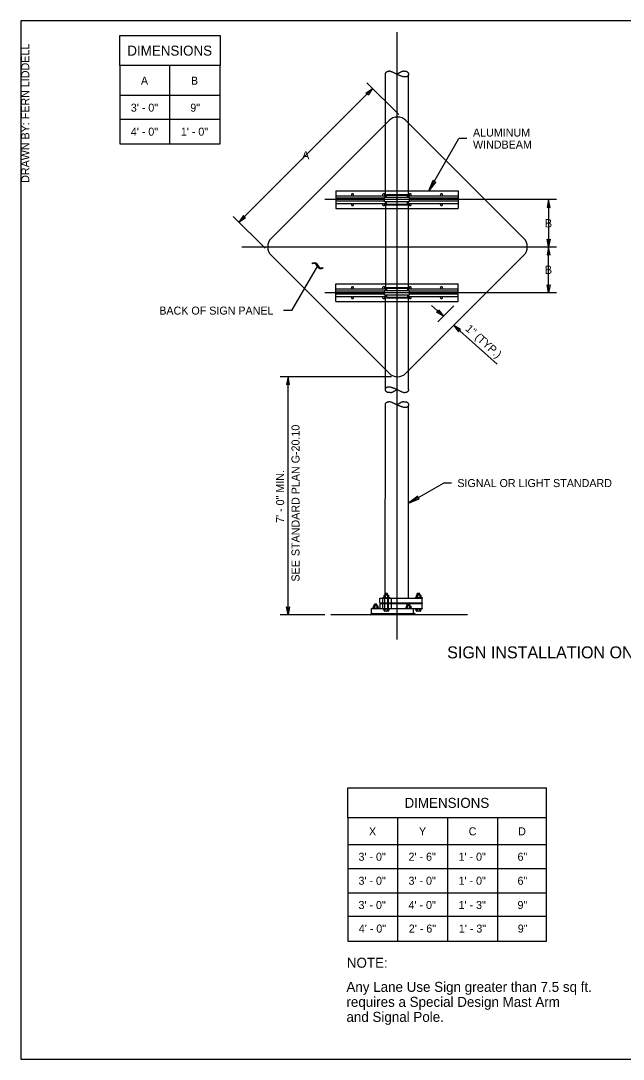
# Model space of a CAD drawing. Extents: x 99862 to 104211, y 98939 to 105076.
# Drawn here: x 99862 to 101066, y 103000 to 105076 of the extents above; entities that cross this region are included whole.
import ezdxf

# ---------------------------------------------------------------- set-up
doc = ezdxf.new("R2010")
doc.units = 0
for name, color, linetype in [('Level 1', 7, 'Continuous'), ('Level 15', 7, 'Continuous'), ('Level 18', 7, 'Continuous'), ('Level 19', 7, 'Continuous'), ('Level 2', 7, 'Continuous'), ('Level 20', 7, 'Continuous'), ('Level 3', 7, 'Continuous'), ('Level 40', 7, 'Continuous'), ('Level 6', 7, 'Continuous'), ('Level 60', 7, 'Continuous'), ('Level 62', 7, 'Continuous'), ('Level 7', 7, 'Continuous')]:
    doc.layers.add(name, color=color, linetype=linetype)

msp = doc.modelspace()

# ---------------------------------------------------------------- linework, layer by layer
at = {"layer": 'Level 1'}
for p, q in [((100590.9, 104868.6), (100362.5, 104640.3)), ((100590.9, 104868.6), (100598.3, 104876)), ((100598.3, 104876), (100598.3, 104876)), ((100632, 104876), (100631.9, 104876)), ((100631.9, 104876), (100637.1, 104870.9)), ((100867.7, 104640.3), (100637.1, 104870.9)), ((100362.5, 104606.6), (100590.9, 104378.3)), ((100637.1, 104376.1), (100867.7, 104606.6)), ((100598.3, 104370.9), (100590.9, 104378.3)), ((100598.3, 104370.9), (100598.3, 104370.9)), ((100637.1, 104376.1), (100631.9, 104370.9)), ((100631.9, 104370.9), (100631.9, 104370.9))]:
    msp.add_line(p, q, dxfattribs=at)
msp.add_lwpolyline([(99862, 102999.5), (103151, 102999.5), (103151, 105075.5), (99862, 105075.5)], close=True, dxfattribs=at)
for centre, start, end in [((100615.1, 104859.2), 44.9963, 134.9997), ((100379.4, 104623.5), 134.9966, 224.9936), ((100850.8, 104623.5), 314.9994, 44.9948), ((100615.1, 104387.7), 225, 314.9996)]:
    msp.add_arc(centre, 23.8, start, end, dxfattribs=at)
at = {"layer": 'Level 15'}
for p, q in [((100614.2, 103838.8), (100614.2, 105052.4)), ((100617.7, 104887.8), (100554.1, 104951.4)), ((100298.2, 104672.9), (100565.4, 104940.1)), ((100677.7, 104735.5), (100738, 104840)), ((100754, 104840), (100738, 104840)), ((100933.1, 104717.9), (100470, 104717.9)), ((100917.1, 104717.9), (100917.1, 104623.5)), ((100350.5, 104620.6), (100286.9, 104684.2)), ((100303.6, 104623.5), (100933.1, 104623.5)), ((100917.1, 104531.9), (100917.1, 104623.5)), ((100444.8, 104589.6), (100446, 104591.3)), ((100448.4, 104590.3), (100444.8, 104589.6)), ((100446, 104591.3), (100448.1, 104591.9)), ((100448.1, 104591.9), (100449.8, 104592.1)), ((100450.1, 104590.1), (100448.4, 104590.3)), ((100449.8, 104592.1), (100451.4, 104591.8)), ((100451.4, 104589.5), (100450.1, 104590.1)), ((100451.4, 104591.8), (100452.9, 104591)), ((100452.5, 104588.5), (100451.4, 104589.5)), ((100452.9, 104591), (100454.7, 104589.4)), ((100454.7, 104589.4), (100456.7, 104585.8)), ((100455.4, 104585.9), (100403.5, 104496.1)), ((100453.7, 104586.4), (100452.5, 104588.5)), ((100456, 104582.6), (100453.7, 104586.4)), ((100457.9, 104580.7), (100456, 104582.6)), ((100456.7, 104585.8), (100458.1, 104583.6)), ((100459.5, 104579.9), (100457.9, 104580.7)), ((100458.1, 104583.6), (100459.4, 104582.3)), ((100459.4, 104582.3), (100460.6, 104581.7)), ((100461.2, 104579.6), (100459.5, 104579.9)), ((100460.6, 104581.7), (100462, 104581.5)), ((100463, 104579.8), (100461.2, 104579.6)), ((100462, 104581.5), (100463.7, 104581.6)), ((100464.9, 104580.4), (100463, 104579.8)), ((100463.7, 104581.6), (100466, 104582.2)), ((100466, 104582.2), (100464.9, 104580.4)), ((100933.1, 104531.9), (100470, 104531.9)), ((100683, 104506), (100706.9, 104484.7)), ((100403.5, 104496.1), (100387.5, 104496.1)), ((100814.4, 104388.9), (100727.4, 104466.4)), ((100603.1, 104363.9), (100380.5, 104363.9)), ((100396.5, 103887.9), (100396.5, 104363.9)), ((100637.2, 104111.2), (100706.7, 104151.3)), ((100722.7, 104151.3), (100706.7, 104151.3)), ((100469.6, 103887.9), (100380.5, 103887.9))]:
    msp.add_line(p, q, dxfattribs=at)
for points in [[(100565.4, 104940.1), (100556.4, 104926.8), (100554.8, 104929.5), (100552.1, 104931.1)], [(100677.7, 104735.5), (100686.5, 104756.7), (100688.6, 104754.3), (100691.7, 104753.7)], [(100917.1, 104717.9), (100914, 104702.2), (100917.1, 104702.9), (100920.2, 104702.2)], [(100298.2, 104672.9), (100311.5, 104681.9), (100308.8, 104683.5), (100307.2, 104686.2)], [(100917.1, 104623.5), (100914, 104639.2), (100917.1, 104638.5), (100920.2, 104639.2)], [(100917.1, 104623.5), (100914, 104607.8), (100917.1, 104608.5), (100920.2, 104607.8)], [(100917.1, 104531.9), (100914, 104547.6), (100917.1, 104546.9), (100920.2, 104547.6)], [(100706.9, 104484.7), (100693.1, 104492.9), (100695.7, 104494.7), (100697.2, 104497.5)], [(100727.4, 104466.4), (100737.1, 104453.6), (100738.6, 104456.4), (100741.2, 104458.2)], [(100396.5, 104363.9), (100393.4, 104348.2), (100396.5, 104348.9), (100399.5, 104348.2)], [(100637.2, 104111.2), (100658.4, 104120), (100656, 104122.1), (100655.4, 104125.2)], [(100396.5, 103887.9), (100393.4, 103903.6), (100396.5, 103902.9), (100399.5, 103903.6)]]:
    msp.add_lwpolyline(points, close=True, dxfattribs=at)
msp.add_lwpolyline([(100727.9, 104505.8), (100695.6, 104473.4)], dxfattribs=at)
at = {"layer": 'Level 18'}
for p, q in [((100588, 103926.8), (100588, 103922.7)), ((100596.1, 103927.2), (100589.1, 103927.2)), ((100590.1, 103927.2), (100590.1, 103930.5)), ((100595.1, 103930.5), (100590.1, 103930.5)), ((100590.3, 103926.9), (100590.3, 103922.7)), ((100591.4, 103928.9), (100593.9, 103928.9)), ((100595, 103926.9), (100595, 103922.7)), ((100595.1, 103927.2), (100595.1, 103930.5)), ((100597.3, 103926.8), (100597.3, 103922.7)), ((100652.6, 103926.8), (100652.6, 103922.7)), ((100660.7, 103927.2), (100653.7, 103927.2)), ((100654.7, 103927.2), (100654.7, 103930.5)), ((100659.7, 103930.5), (100654.7, 103930.5)), ((100654.9, 103926.9), (100654.9, 103922.7)), ((100656, 103928.9), (100658.5, 103928.9)), ((100659.6, 103926.9), (100659.6, 103922.7)), ((100659.7, 103927.2), (100659.7, 103930.5)), ((100661.9, 103926.8), (100661.9, 103922.7)), ((100566.7, 103905.5), (100566.7, 103901.4)), ((100574.8, 103905.9), (100567.8, 103905.9)), ((100568.8, 103905.9), (100568.8, 103909.2)), ((100573.8, 103909.2), (100568.8, 103909.2)), ((100569, 103905.5), (100569, 103901.4)), ((100570.1, 103907.6), (100572.6, 103907.6)), ((100573.6, 103905.6), (100573.6, 103901.4)), ((100573.8, 103905.9), (100573.8, 103909.2)), ((100575.9, 103905.5), (100575.9, 103901.4)), ((100579.6, 103911.7), (100579.6, 103921.5)), ((100579.6, 103921.5), (100664.1, 103921.5)), ((100579.6, 103911.7), (100664.1, 103911.7)), ((100579.6, 103910.4), (100664.1, 103910.4)), ((100579.6, 103910.4), (100579.6, 103900.6)), ((100585.8, 103922.7), (100599.7, 103922.7)), ((100585.8, 103922.7), (100585.8, 103921.5)), ((100585.8, 103911.7), (100585.8, 103921.5)), ((100585.8, 103911.7), (100585.8, 103910.4)), ((100585.8, 103900.6), (100585.8, 103910.4)), ((100589.5, 103911.7), (100589.5, 103921.5)), ((100589.5, 103900.6), (100589.5, 103910.4)), ((100595.6, 103911.7), (100595.6, 103921.5)), ((100595.6, 103900.6), (100595.6, 103910.4)), ((100596.9, 103911.7), (100596.9, 103921.5)), ((100596.9, 103900.6), (100596.9, 103910.4)), ((100599.7, 103922.7), (100599.7, 103921.5)), ((100599.7, 103911.7), (100599.7, 103910.4)), ((100603, 103911.7), (100603, 103921.5)), ((100603, 103900.6), (100603, 103910.4)), ((100632.3, 103905.5), (100632.3, 103901.4)), ((100640.4, 103905.9), (100633.4, 103905.9)), ((100634.4, 103905.9), (100634.4, 103909.2)), ((100639.4, 103909.2), (100634.4, 103909.2)), ((100634.6, 103905.5), (100634.6, 103901.4)), ((100635.7, 103907.6), (100638.2, 103907.6)), ((100639.3, 103905.6), (100639.3, 103901.4)), ((100639.4, 103905.9), (100639.4, 103909.2)), ((100641.6, 103905.5), (100641.6, 103901.4)), ((100650.2, 103922.7), (100664.1, 103922.7)), ((100650.2, 103922.7), (100650.2, 103921.5)), ((100650.2, 103911.7), (100650.2, 103910.4)), ((100664.1, 103922.7), (100664.1, 103921.5)), ((100664.1, 103911.7), (100664.1, 103921.5)), ((100664.1, 103911.7), (100664.1, 103910.4)), ((100664.1, 103900.6), (100664.1, 103910.4)), ((100755.3, 103887.9), (100481.6, 103887.9)), ((100559.9, 103887.9), (100562.8, 103890.7)), ((100562.8, 103890.7), (100562.8, 103900.6)), ((100562.8, 103900.6), (100579.6, 103900.6)), ((100562.8, 103890.7), (100648.5, 103890.7)), ((100564, 103901.4), (100578.4, 103901.4)), ((100564, 103901.4), (100564, 103900.6)), ((100578.4, 103901.4), (100578.4, 103900.6)), ((100579.6, 103900.6), (100664.1, 103900.6)), ((100585.8, 103900.6), (100585.8, 103899.8)), ((100585.8, 103899.8), (100599.7, 103899.8)), ((100588.2, 103895.7), (100588.2, 103899.8)), ((100596.3, 103895.3), (100589.4, 103895.3)), ((100590.5, 103895.6), (100590.5, 103899.8)), ((100595.2, 103895.6), (100595.2, 103899.8)), ((100597.5, 103895.7), (100597.5, 103899.8)), ((100599.7, 103900.6), (100599.7, 103899.8)), ((100629.7, 103901.4), (100644, 103901.4)), ((100629.7, 103901.4), (100629.7, 103900.6)), ((100644, 103901.4), (100644, 103900.6)), ((100646.9, 103890.7), (100646.9, 103900.6)), ((100651.4, 103887.9), (100648.5, 103890.7)), ((100650.2, 103900.6), (100650.2, 103899.8)), ((100650.2, 103899.8), (100664.1, 103899.8)), ((100652.6, 103895.7), (100652.6, 103899.8)), ((100660.7, 103895.3), (100653.7, 103895.3)), ((100654.9, 103895.6), (100654.9, 103899.8)), ((100659.6, 103895.6), (100659.6, 103899.8)), ((100661.9, 103895.7), (100661.9, 103899.8)), ((100664.1, 103900.6), (100664.1, 103899.8))]:
    msp.add_line(p, q, dxfattribs=at)
for centre, radius, start, end in [((100589.2, 103925.4), 1.81, 52.3034, 130.9523), ((100592.7, 103919.5), 7.78, 72.912, 107.9146), ((100596.1, 103925.3), 1.95, 52.6587, 124.5047), ((100653.8, 103925.4), 1.81, 52.3034, 130.9523), ((100657.3, 103919.5), 7.78, 72.912, 107.9146), ((100660.7, 103925.3), 1.95, 52.6587, 124.5047), ((100567.9, 103904.1), 1.81, 52.3034, 130.9523), ((100571.4, 103898.1), 7.78, 72.912, 107.9146), ((100574.8, 103904), 1.95, 52.6587, 124.5047), ((100633.5, 103904.1), 1.81, 52.3034, 130.9523), ((100637, 103898.1), 7.78, 72.912, 107.9146), ((100640.4, 103904), 1.95, 52.6587, 124.5047), ((100589.4, 103897.1), 1.81, 229.0477, 307.6966), ((100592.9, 103903), 7.78, 252.0854, 287.088), ((100596.3, 103897.2), 1.95, 235.4953, 307.3413), ((100653.8, 103897.1), 1.81, 229.0477, 307.6966), ((100657.3, 103903), 7.78, 252.0854, 287.088), ((100660.7, 103897.2), 1.95, 235.4953, 307.3413)]:
    msp.add_arc(centre, radius, start, end, dxfattribs=at)
at = {"layer": 'Level 19'}
for p, q in [((100590.9, 104722.6), (100590.9, 104968.9)), ((100637.1, 104722.6), (100637.1, 104967.4)), ((100590.9, 104713.2), (100590.9, 104536.6)), ((100637.1, 104536.6), (100637.1, 104713.2)), ((100590.9, 104338.7), (100590.9, 104527.2)), ((100637.1, 104338.4), (100637.1, 104527.2)), ((100590.7, 103930.5), (100591, 104309.7)), ((100637.2, 103921.5), (100637.2, 104306.4))]:
    msp.add_line(p, q, dxfattribs=at)
for points in [[(100627.4, 104974.7), (100630.4, 104974.7)], [(100600.7, 104332.2), (100597.7, 104332.2)], [(100627.5, 104314), (100630.5, 104314)]]:
    msp.add_lwpolyline(points, dxfattribs=at)
for points in [[(100590.9, 104968.5), (100590.9, 104968.6), (100590.9, 104969), (100591, 104969.8), (100591.3, 104970.7), (100591.8, 104971.6), (100592.4, 104972.5), (100593.3, 104973.3), (100594.4, 104974), (100595.8, 104974.6), (100597, 104974.7), (100597.6, 104974.7)], [(100630.4, 104974.7), (100631, 104974.7), (100632.2, 104974.6), (100633.6, 104974), (100634.7, 104973.3), (100635.6, 104972.5), (100636.2, 104971.6), (100636.7, 104970.7), (100637, 104969.8), (100637.2, 104968.8), (100637.2, 104967.7), (100637, 104967), (100636.7, 104966.1), (100636.1, 104965.3), (100635.4, 104964.6), (100634.3, 104963.9), (100633, 104963.4), (100631.4, 104963.2), (100629.5, 104963.2), (100627.4, 104963.4), (100625.3, 104963.9), (100623.2, 104964.5), (100621.1, 104965.3), (100619.1, 104966.1), (100617.1, 104967), (100615.1, 104967.9), (100613.2, 104968.8), (100611.3, 104969.8), (100609.4, 104970.7), (100607.5, 104971.6), (100605.6, 104972.5), (100603.7, 104973.3), (100601.7, 104974), (100599.7, 104974.6), (100598.3, 104974.7), (100597.7, 104974.7)], [(100627.4, 104974.7), (100626.9, 104974.7), (100625.8, 104974.6), (100624.1, 104974), (100622.5, 104973.3), (100620.9, 104972.5), (100619.4, 104971.6), (100617.8, 104970.7), (100616.3, 104969.8), (100615, 104969), (100614.3, 104968.6), (100614.1, 104968.4)], [(100597.7, 104332.2), (100597.1, 104332.2), (100595.9, 104332.3), (100594.5, 104332.9), (100593.4, 104333.6), (100592.5, 104334.4), (100591.9, 104335.3), (100591.4, 104336.2), (100591.1, 104337.1), (100590.9, 104338.1), (100590.9, 104338.7), (100591.1, 104339.9), (100591.4, 104340.7), (100592, 104341.6), (100592.7, 104342.3), (100593.8, 104343), (100595.1, 104343.5), (100596.7, 104343.7), (100598.6, 104343.7), (100600.7, 104343.5), (100602.8, 104343), (100604.9, 104342.3), (100607, 104341.6), (100609, 104340.8), (100611, 104339.9), (100612.9, 104339), (100614.9, 104338.1), (100616.8, 104337.1), (100618.7, 104336.2), (100620.6, 104335.3), (100622.5, 104334.4), (100624.4, 104333.6), (100626.4, 104332.9), (100628.4, 104332.3), (100629.7, 104332.2), (100630.4, 104332.2)], [(100600.7, 104332.2), (100601.2, 104332.2), (100602.3, 104332.3), (100604, 104332.9), (100605.6, 104333.6), (100607.1, 104334.4), (100608.7, 104335.3), (100610.3, 104336.2), (100611.8, 104337.1), (100613.1, 104337.9), (100613.8, 104338.3), (100614, 104338.4)], [(100637.1, 104338.4), (100637.1, 104338.3), (100637.1, 104337.9), (100637, 104337.1), (100636.7, 104336.2), (100636.2, 104335.3), (100635.6, 104334.4), (100634.7, 104333.6), (100633.6, 104332.9), (100632.2, 104332.3), (100631, 104332.2), (100630.4, 104332.2)], [(100591, 104309.7), (100591, 104309.8), (100591.2, 104310.2), (100591.5, 104310.9), (100592.2, 104311.8), (100593.1, 104312.6), (100594.2, 104313.3), (100595.6, 104313.9), (100596.8, 104314), (100597.5, 104314)], [(100630.5, 104314), (100631.1, 104314), (100632.3, 104313.9), (100633.7, 104313.3), (100634.8, 104312.6), (100635.7, 104311.8), (100636.4, 104310.9), (100636.9, 104310), (100637.2, 104309), (100637.3, 104308.1), (100637.3, 104307.2), (100637.1, 104306.3), (100636.8, 104305.4), (100636.3, 104304.6), (100635.5, 104303.8), (100634.5, 104303.1), (100633.1, 104302.6), (100631.5, 104302.4), (100629.6, 104302.4), (100627.5, 104302.6), (100625.3, 104303.1), (100623.2, 104303.8), (100621.1, 104304.5), (100619, 104305.4), (100617, 104306.2), (100615.1, 104307.2), (100613.1, 104308.1), (100611.2, 104309), (100609.3, 104310), (100607.4, 104310.9), (100605.4, 104311.8), (100603.5, 104312.6), (100601.5, 104313.3), (100599.4, 104313.9), (100598.1, 104314), (100597.5, 104314)], [(100627.5, 104314), (100626.9, 104314), (100625.8, 104313.9), (100624.1, 104313.3), (100622.5, 104312.6), (100620.9, 104311.8), (100619.3, 104310.9), (100617.8, 104310), (100616.2, 104309), (100615, 104308.3), (100614.2, 104307.8), (100614, 104307.7)]]:
    msp.add_open_spline(points, degree=3, dxfattribs=at)
at = {"layer": 'Level 2'}
for p, q in [((100491.6, 104735.5), (100491.6, 104700.3)), ((100491.6, 104735.5), (100590.9, 104735.5)), ((100590.9, 104735.5), (100637.1, 104735.5)), ((100637.1, 104735.5), (100736.4, 104735.5)), ((100736.4, 104735.5), (100736.4, 104700.3)), ((100491.6, 104725.7), (100590.9, 104725.7)), ((100589.3, 104721), (100491.6, 104721)), ((100589.3, 104714.8), (100491.6, 104714.8)), ((100637.1, 104725.7), (100736.4, 104725.7)), ((100736.4, 104721), (100638.7, 104721)), ((100736.4, 104714.8), (100638.7, 104714.8)), ((100491.6, 104710.1), (100590.9, 104710.1)), ((100491.6, 104700.3), (100590.9, 104700.3)), ((100590.9, 104700.3), (100637.1, 104700.3)), ((100637.1, 104710.1), (100736.4, 104710.1)), ((100637.1, 104700.3), (100736.4, 104700.3)), ((100491.6, 104514.3), (100491.6, 104549.4)), ((100491.6, 104549.4), (100590.9, 104549.4)), ((100590.9, 104549.4), (100637.1, 104549.4)), ((100637.1, 104549.4), (100736.4, 104549.4)), ((100736.4, 104514.3), (100736.4, 104549.4)), ((100491.6, 104539.7), (100590.9, 104539.7)), ((100589.3, 104535), (100491.6, 104535)), ((100589.3, 104528.7), (100491.6, 104528.7)), ((100637.1, 104539.7), (100736.4, 104539.7)), ((100736.4, 104535), (100638.7, 104535)), ((100736.4, 104528.7), (100638.7, 104528.7)), ((100491.6, 104524), (100590.9, 104524)), ((100491.6, 104514.3), (100590.9, 104514.3)), ((100590.9, 104514.3), (100637.1, 104514.3)), ((100637.1, 104524), (100736.4, 104524)), ((100637.1, 104514.3), (100736.4, 104514.3))]:
    msp.add_line(p, q, dxfattribs=at)
at = {"layer": 'Level 3'}
for p, q in [((100630.4, 104963.2), (100630.4, 104963.2)), ((100592.9, 104726.8), (100592.9, 104727.9)), ((100592.9, 104727.9), (100635.1, 104727.9)), ((100592.9, 104722.6), (100592.9, 104726.8)), ((100592.9, 104726.8), (100635.1, 104726.8)), ((100635.1, 104726.8), (100635.1, 104727.9)), ((100635.1, 104722.6), (100635.1, 104726.8)), ((100592.9, 104708.7), (100592.9, 104713.2)), ((100592.9, 104708.7), (100592.9, 104707.6)), ((100592.9, 104708.7), (100635.1, 104708.7)), ((100592.9, 104707.6), (100635.1, 104707.6)), ((100635.1, 104708.7), (100635.1, 104713.2)), ((100635.1, 104708.7), (100635.1, 104707.6)), ((100592.9, 104541.1), (100592.9, 104542.2)), ((100592.9, 104542.2), (100635.1, 104542.2)), ((100592.9, 104541.1), (100635.1, 104541.1)), ((100592.9, 104541.1), (100592.9, 104536.6)), ((100592.9, 104527.2), (100592.9, 104523)), ((100635.1, 104541.1), (100635.1, 104542.2)), ((100635.1, 104541.1), (100635.1, 104536.6)), ((100635.1, 104527.2), (100635.1, 104523)), ((100592.9, 104523), (100635.1, 104523)), ((100592.9, 104521.9), (100635.1, 104521.9)), ((100635.1, 104523), (100635.1, 104521.9)), ((100630.5, 104302.4), (100630.5, 104302.4))]:
    msp.add_line(p, q, dxfattribs=at)
at = {"layer": 'Level 40'}
for p, q in [((100160.3, 104829.8), (100160.3, 104985.8)), ((100260.3, 104925.8), (100060.3, 104925.8)), ((100260.3, 104877.8), (100060.3, 104877.8)), ((100515.5, 103542), (100913.2, 103542)), ((100515.5, 103482), (100515.5, 103542)), ((100913.2, 103235.3), (100913.2, 103542)), ((100615.5, 103482), (100515.5, 103482)), ((100515.5, 103482), (100515.5, 103428.3)), ((100615.5, 103235.3), (100615.5, 103482)), ((100715.5, 103482), (100615.5, 103482)), ((100715.5, 103235.3), (100715.5, 103482)), ((100815.5, 103482), (100715.5, 103482)), ((100815.5, 103235.3), (100815.5, 103482)), ((100913.2, 103482), (100815.5, 103482)), ((100913.2, 103428.3), (100515.5, 103428.3)), ((100515.5, 103428.3), (100515.5, 103235.3)), ((100913.2, 103380.3), (100515.5, 103380.3)), ((100913.2, 103331.8), (100515.5, 103331.8)), ((100913.8, 103284.7), (100516, 103284.7)), ((100515.5, 103235.3), (100913.2, 103235.3))]:
    msp.add_line(p, q, dxfattribs=at)
for points in [[(100060.3, 105045.8), (100260.3, 105045.8), (100260.3, 104985.8), (100060.3, 104985.8)], [(100260.3, 104985.8), (100060.3, 104985.8), (100060.3, 104829.8), (100260.3, 104829.8)]]:
    msp.add_lwpolyline(points, close=True, dxfattribs=at)
at = {"layer": 'Level 6'}
for centre, start, end in [((100525.1, 104727.5), 90, 230.0555), ((100525.1, 104727.5), 309.9445, 90), ((100587.6, 104727.5), 90, 230.0555), ((100587.6, 104727.5), 309.9445, 90), ((100640.4, 104727.5), 90, 230.0555), ((100640.4, 104727.5), 309.9445, 90), ((100702.9, 104727.5), 90, 230.0555), ((100702.9, 104727.5), 309.9445, 90), ((100525.1, 104708.3), 129.9445, 270), ((100525.1, 104708.3), 270, 50.0555), ((100587.6, 104708.3), 129.9445, 270), ((100587.6, 104708.3), 270, 50.0555), ((100640.4, 104708.3), 129.9445, 270), ((100640.4, 104708.3), 270, 50.0555), ((100702.9, 104708.3), 129.9445, 270), ((100702.9, 104708.3), 270, 50.0555), ((100525.1, 104541.5), 90, 230.0555), ((100525.1, 104541.5), 309.9445, 90), ((100587.6, 104541.5), 90, 230.0555), ((100587.6, 104541.5), 309.9445, 90), ((100640.4, 104541.5), 90, 230.0555), ((100640.4, 104541.5), 309.9445, 90), ((100702.9, 104541.5), 90, 230.0555), ((100702.9, 104541.5), 309.9445, 90), ((100525.1, 104522.3), 129.9445, 270), ((100525.1, 104522.3), 270, 50.0555), ((100587.6, 104522.3), 129.9445, 270), ((100587.6, 104522.3), 270, 50.0555), ((100640.4, 104522.3), 129.9445, 270), ((100640.4, 104522.3), 270, 50.0555), ((100702.9, 104522.3), 129.9445, 270), ((100702.9, 104522.3), 270, 50.0555)]:
    msp.add_arc(centre, 2.34, start, end, dxfattribs=at)
at = {"layer": 'Level 60'}
msp.add_line((99862, 102999.5), (99862, 102999.5), dxfattribs=at)
at = {"layer": 'Level 7'}
for p, q in [((100589.3, 104713.2), (100589.3, 104722.6)), ((100589.3, 104722.6), (100638.7, 104722.6)), ((100638.7, 104722.6), (100638.7, 104713.2)), ((100638.7, 104713.2), (100589.3, 104713.2)), ((100589.4, 104527.2), (100589.4, 104536.6)), ((100589.4, 104536.6), (100638.5, 104536.6)), ((100638.5, 104527.2), (100589.4, 104527.2)), ((100638.5, 104536.6), (100638.5, 104527.2))]:
    msp.add_line(p, q, dxfattribs=at)

# ---------------------------------------------------------------- texts
at = {"layer": 'Level 20'}
for s, height, p in [('DIMENSIONS', 20, (100075, 105005.8)), ('A', 16, (100102.2, 104947.8)), ('B', 16, (100202.2, 104947.8)), ('3\' - 0"', 16, (100082, 104893.8)), ('9"', 16, (100200.9, 104893.8)), ('4\' - 0"', 16, (100082, 104845.8)), ('1\' - 0"', 16, (100182, 104845.8)), ('A', 16.5, (100424.2, 104798.3)), ('B', 16.5, (100909.5, 104662.4)), ('B', 16.5, (100909.5, 104569.4)), ('BACK OF SIGN PANEL', 16, (100138.9, 104488.1)), ('SIGN INSTALLATION ON SIGNAL OR LIGHT STANDARD', 24, (100714.4, 103800.9)), ('DIMENSIONS', 20, (100629.1, 103502)), ('X', 16, (100558, 103447.1)), ('Y', 16, (100658, 103447.1)), ('C', 16, (100757.4, 103447.1)), ('D', 16, (100856.3, 103447.1)), ('3\' - 0"', 16, (100537.1, 103396.3)), ('2\' - 6"', 16, (100637.1, 103396.3)), ('1\' - 0"', 16, (100737.1, 103396.3)), ('6"', 16, (100855, 103396.3)), ('3\' - 0"', 16, (100537.1, 103348.3)), ('3\' - 0"', 16, (100637.1, 103348.3)), ('1\' - 0"', 16, (100737.1, 103348.3)), ('6"', 16, (100855, 103348.3)), ('3\' - 0"', 16, (100537.1, 103299.8)), ('4\' - 0"', 16, (100637.1, 103299.8)), ('1\' - 3"', 16, (100737.1, 103299.8)), ('9"', 16, (100855, 103299.8)), ('4\' - 0"', 16, (100537.7, 103252.7)), ('2\' - 6"', 16, (100637.7, 103252.7)), ('1\' - 3"', 16, (100737.7, 103252.7)), ('9"', 16, (100855.5, 103252.7)), ('NOTE:', 20, (100513.8, 103182.4)), ('Any Lane Use Sign greater than 7.5 sq ft. ', 20, (100513, 103134.2)), ('requires a Special Design Mast Arm ', 20, (100513, 103104.2)), ('and Signal Pole.', 20, (100513, 103074.2))]:
    msp.add_text(s, height=height, dxfattribs=at).set_placement(p)
for s, rotation, p in [('ALUMINUM', 360, (100766, 104844)), ('WINDBEAM', 360, (100766, 104820)), ('1" (TYP.)', 318.3041, (100749.5, 104457.9)), ('STANDARD PLAN G-20.10', 90, (100419.2, 104005.3)), ('7\' - 0" MIN.', 90, (100388.5, 104071.7)), ('SIGNAL OR LIGHT STANDARD', 360, (100734.7, 104143.3)), ('SEE ', 90, (100419.2, 103954.4))]:
    msp.add_text(s, height=16, rotation=rotation, dxfattribs=at).set_placement(p)
at = {"layer": 'Level 62'}
msp.add_text('DRAWN BY: FERN LIDDELL', height=16, rotation=90, dxfattribs=at).set_placement((99879, 104751.5))

doc.saveas('drawing.dxf')
